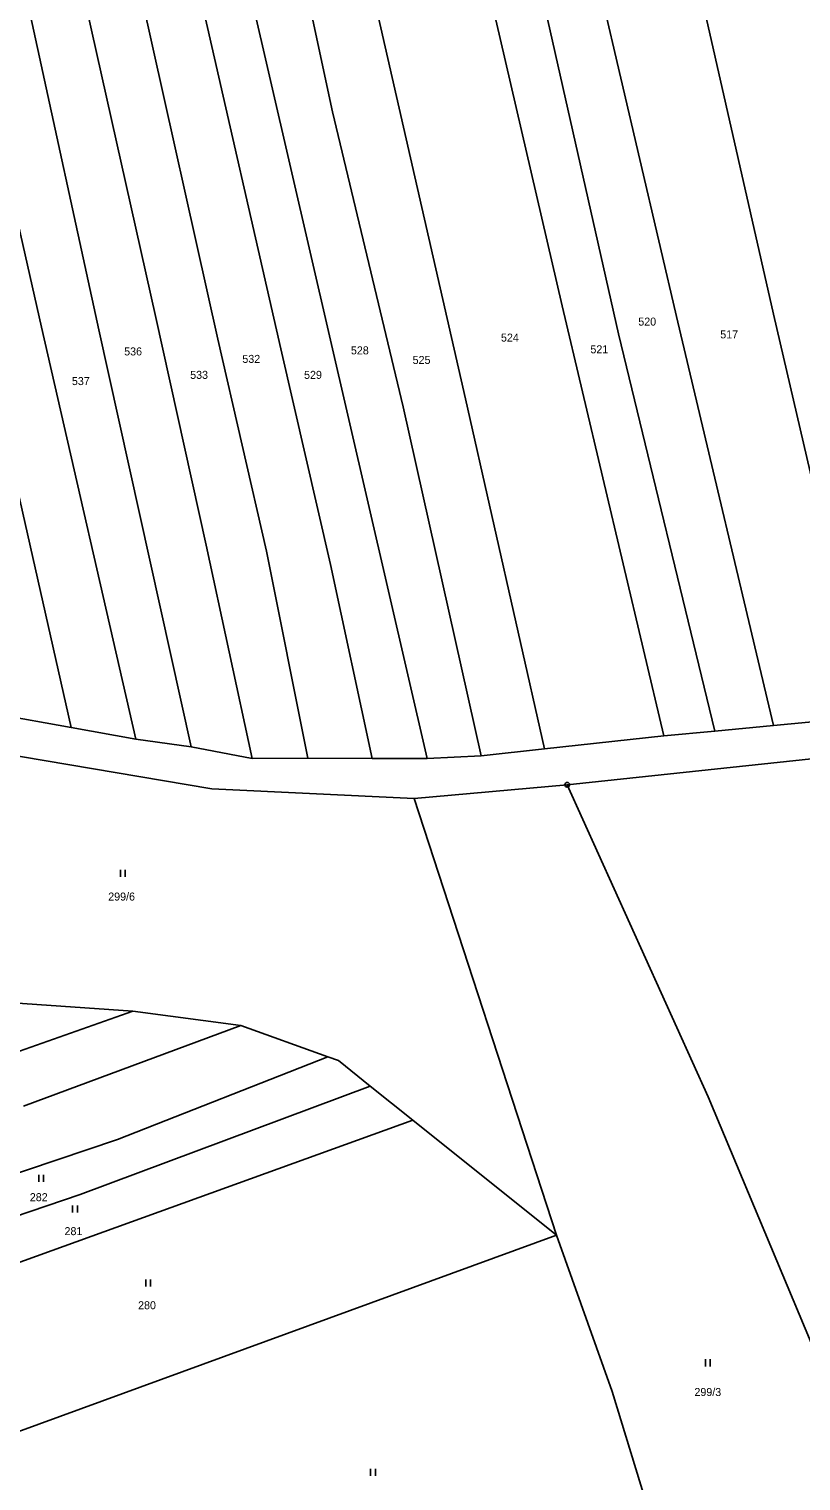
# Model space of a CAD drawing. Extents: x -820420 to -815896, y -1105820 to -1103643.
# Drawn here: x -817052 to -816887.9, y -1104919.6 to -1104611.1 of the extents above; entities that cross this region are included whole.
import ezdxf
from ezdxf.enums import TextEntityAlignment as Align

# ---------------------------------------------------------------- set-up
doc = ezdxf.new("R2010")
doc.units = 0
doc.header["$LTSCALE"] = 0.68
for name, color, linetype, lineweight in [('1', 7, 'Continuous', 25), ('3', 7, 'Continuous', 25), ('8', 7, 'Continuous', 25)]:
    doc.layers.add(name, color=color, linetype=linetype, lineweight=lineweight)
doc.layers.add('2', color=7, linetype='Continuous')

msp = doc.modelspace()

# ---------------------------------------------------------------- linework, layer by layer
at = {"layer": '1'}
for p, q in [((-816980.65, -1104595.8), (-816959.27, -1104689.64)), ((-816938.71, -1104669.9), (-816955.72, -1104596.46)), ((-816987.52, -1104628.71), (-816993.92, -1104598.92)), ((-816926.74, -1104675.83), (-816944.24, -1104598.34)), ((-816998.48, -1104679.04), (-817015.93, -1104602.82)), ((-817005.57, -1104601.08), (-816967.43, -1104766.08)), ((-816931.05, -1104600.98), (-816914.08, -1104673.39)), ((-817039.81, -1104606.57), (-817025.06, -1104672.4)), ((-817027.95, -1104604.85), (-817011.88, -1104676.99)), ((-816908.83, -1104605.5), (-816893.76, -1104671.67)), ((-817051.71, -1104608.28), (-817037.19, -1104675.03)), ((-816972.47, -1104691.39), (-816987.52, -1104628.71)), ((-816917.07, -1104761.29), (-816938.71, -1104669.9)), ((-817029.36, -1104762), (-817049.39, -1104674.46)), ((-817025.06, -1104672.4), (-817014.39, -1104720.73)), ((-816893.77, -1104759.09), (-816914.08, -1104673.39)), ((-816873.95, -1104757.22), (-816893.76, -1104671.67)), ((-817043.08, -1104759.53), (-817062.06, -1104675.48)), ((-817017.55, -1104763.59), (-817037.19, -1104675.03)), ((-817011.88, -1104676.99), (-817001.54, -1104722.03)), ((-816906.23, -1104760.27), (-816926.74, -1104675.83)), ((-816987.95, -1104724.86), (-816998.48, -1104679.04)), ((-816959.27, -1104689.64), (-816942.49, -1104764.03)), ((-816955.93, -1104765.52), (-816972.47, -1104691.39)), ((-817014.39, -1104720.73), (-817004.62, -1104766.06)), ((-817001.54, -1104722.03), (-816992.78, -1104766.01)), ((-816979.11, -1104766.11), (-816987.95, -1104724.86)), ((-817146.47, -1104749.9), (-817013.14, -1104772.55)), ((-817043.08, -1104759.53), (-817068.88, -1104754.87)), ((-816873.95, -1104757.22), (-816893.77, -1104759.09)), ((-817029.36, -1104762), (-817043.08, -1104759.53)), ((-816906.23, -1104760.27), (-816917.07, -1104761.29)), ((-816893.77, -1104759.09), (-816906.23, -1104760.27)), ((-817017.55, -1104763.59), (-817029.36, -1104762)), ((-816942.49, -1104764.03), (-816955.93, -1104765.52)), ((-816917.07, -1104761.29), (-816942.49, -1104764.03)), ((-816937.63, -1104771.65), (-816857.2, -1104763.1)), ((-816979.11, -1104766.11), (-816992.78, -1104766.01)), ((-816967.43, -1104766.08), (-816979.11, -1104766.11)), ((-816955.93, -1104765.52), (-816967.43, -1104766.08)), ((-817013.14, -1104772.55), (-816970.19, -1104774.61)), ((-816970.19, -1104774.61), (-816937.63, -1104771.65)), ((-816937.63, -1104771.65), (-816907.63, -1104837.97)), ((-816970.19, -1104774.61), (-816939.91, -1104867.38)), ((-817055.48, -1104818), (-817029.97, -1104819.74)), ((-817029.97, -1104819.74), (-817131.01, -1104855.32)), ((-817029.97, -1104819.74), (-817007.02, -1104822.84)), ((-817053.19, -1104839.93), (-817007.02, -1104822.84)), ((-817007.02, -1104822.84), (-816988.53, -1104829.45)), ((-816988.53, -1104829.45), (-817033.21, -1104847.02)), ((-816988.53, -1104829.45), (-816986.25, -1104830.25)), ((-816986.25, -1104830.25), (-816979.5, -1104835.67)), ((-817041.18, -1104858.69), (-816979.5, -1104835.67)), ((-816979.5, -1104835.67), (-816970.47, -1104842.9)), ((-816907.63, -1104837.97), (-816873.71, -1104919.19)), ((-817112.29, -1104894.16), (-816970.47, -1104842.9)), ((-816970.47, -1104842.9), (-816939.91, -1104867.38)), ((-817033.21, -1104847.02), (-817065.09, -1104857.79)), ((-817113.99, -1104883.6), (-817041.18, -1104858.69)), ((-816939.91, -1104867.38), (-817059.91, -1104911.14)), ((-816939.91, -1104867.38), (-816928.07, -1104900.57)), ((-816928.07, -1104900.57), (-816915.85, -1104940.3))]:
    msp.add_line(p, q, dxfattribs=at)
for points in [[(-817049.39, -1104674.46), (-817063.96, -1104610.15), (-817076.46, -1104611.84)], [(-816992.78, -1104766.01), (-817004.62, -1104766.06), (-817017.55, -1104763.59)]]:
    msp.add_lwpolyline(points, dxfattribs=at)
at = {"layer": '3'}
for p, q in [((-817032.621, -1104791.26), (-817032.621, -1104789.76)), ((-817031.62, -1104791.26), (-817031.62, -1104789.76)), ((-817049.981, -1104856.01), (-817049.981, -1104854.51)), ((-817048.98, -1104856.01), (-817048.98, -1104854.51)), ((-817042.761, -1104862.56), (-817042.761, -1104861.06)), ((-817041.76, -1104862.56), (-817041.76, -1104861.06)), ((-817027.201, -1104878.29), (-817027.201, -1104876.79)), ((-817026.2, -1104878.29), (-817026.2, -1104876.79)), ((-816908.251, -1104895.23), (-816908.251, -1104893.73)), ((-816907.25, -1104895.23), (-816907.25, -1104893.73)), ((-816979.411, -1104918.47), (-816979.411, -1104916.97)), ((-816978.41, -1104918.47), (-816978.41, -1104916.97))]:
    msp.add_line(p, q, dxfattribs=at)
at = {"layer": '8'}
for radius in [0.5, 0.0303]:
    msp.add_circle((-816937.63, -1104771.6499), radius, dxfattribs=at)

# ---------------------------------------------------------------- texts
at = {"layer": '2'}
for s, p in [('520', (-816920.619, -1104674.105)), ('524', (-816949.809, -1104677.505)), ('517', (-816903.199, -1104676.825)), ('536', (-817029.909, -1104680.445)), ('532', (-817004.789, -1104682.035)), ('528', (-816981.709, -1104680.225)), ('525', (-816968.589, -1104682.255)), ('521', (-816930.799, -1104679.995)), ('533', (-817015.879, -1104685.425)), ('529', (-816991.669, -1104685.425)), ('537', (-817041.019, -1104686.745)), ('299/6', (-817032.35, -1104796.265)), ('282', (-817049.969, -1104860.135)), ('281', (-817042.589, -1104867.355)), ('280', (-817026.949, -1104883.095)), ('299/3', (-816907.74, -1104901.535))]:
    msp.add_text(s, height=1.7, dxfattribs=at).set_placement(p, align=Align.CENTER)

doc.saveas('drawing.dxf')
